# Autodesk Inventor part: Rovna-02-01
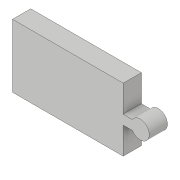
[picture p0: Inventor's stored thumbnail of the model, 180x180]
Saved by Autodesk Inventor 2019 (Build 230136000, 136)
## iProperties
Created: 2019-05
Part Number: Rovna-02-01
Material: Všeobecné
Document SubType Name: Modeling
Density: 1 g/cm^3
Appearance: Výchozí
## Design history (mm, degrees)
sketch "Náčrt1"
  geometry: L1 (35, -20)-(-35, -20); L2 (-35, 20)-(35, 20); L3 (35, -20)-(-35, 20); L4 (-35, -20)-(35, 20); L5 (35, 20)-(35, 3); L6 (35, -3)-(35, -20); L7 (-35, -20)-(-35, 20); L8 (35, 3)-(40.845, 3); L9 (40.845, -3)-(35, -3); L10 (-52.3, 0)-(68.8, 0) reference; A1 r 5.75 centre (45.75, 0) between (40.845, -3) and (40.845, 3); 1 further point
  constraints: 18 end point, 3 parallel, 2 collinear, 2 horizontal, 2 midpoint, 2 point on circle, 1 centre point, 1 perpendicular, 1 point on line
  dimensions: "d0" = 40 distance of L2.end L1.start; "d1" = 70 distance of L2.start L2.end; "d31" = 11.5 diameter of A1; "d33" = 6 distance between parallel lines of L8 L9; "d34" = 16.5 dimension on A1 L6
extrude "Základní tvar" new body sketch "Náčrt1" stored distance "d9" = 11.5; taper "d10" = 0 deg
node "Těleso1"
